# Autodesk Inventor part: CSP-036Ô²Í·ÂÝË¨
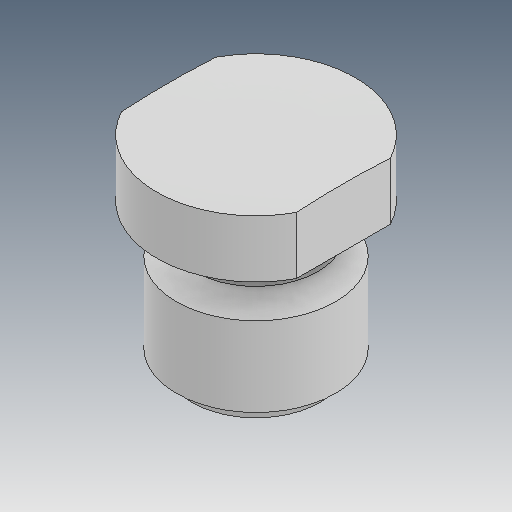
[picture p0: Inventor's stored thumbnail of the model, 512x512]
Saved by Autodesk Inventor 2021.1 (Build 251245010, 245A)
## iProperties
Created: 2019-01
Part Number: CSP-036Ô²Í·ÂÝË¨
Material: Ogólny
Document SubType Name: Modeling
Designer: user
Density: 1 g/cm^3
Appearance: Domyślna
Author: user
Revision Number: ÈÎºÎ
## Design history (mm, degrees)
feature "ÇÐ³ý-À­Éì1"
node "Bryła1"
